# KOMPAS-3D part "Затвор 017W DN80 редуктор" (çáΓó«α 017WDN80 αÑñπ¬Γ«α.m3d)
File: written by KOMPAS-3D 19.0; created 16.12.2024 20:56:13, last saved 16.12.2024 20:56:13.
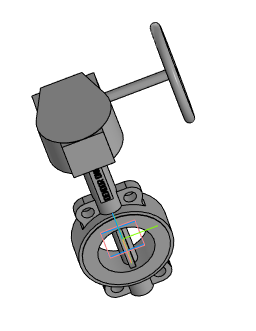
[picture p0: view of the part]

Document properties: Автор: Евгений; Полное имя файла: ..\Затвор 017WDN80 редуктор.a3d

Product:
- Part/product: Затвор 017W DN80 редуктор
    Масса: 11.4804

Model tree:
1. Операция без истории:1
